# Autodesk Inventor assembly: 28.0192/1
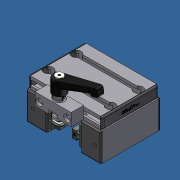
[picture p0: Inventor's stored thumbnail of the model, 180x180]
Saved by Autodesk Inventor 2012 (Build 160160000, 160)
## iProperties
Created: 2007-06
Part Number: 28.0192/1
Document SubType Name: Assembly
Designer: Andy Moles
Description: SLIDE LWN 32X45-45 WITH TOP CLAMP
Author: Andy Moles
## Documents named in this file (3)
- C:\Andys Backup Data\ANDY'S INVENTOR\INVENTOR LIBRARIES\PARTS LIBRARY\READY FOR USE MODULES LG\28.0192_1 SLIDE LWN 32X45-45 WITH TOP CLAMP.iam
- C:\Andys Backup Data\ANDY'S INVENTOR\INVENTOR LIBRARIES\PARTS LIBRARY\COMPONENTS LR\28.0270_9 SLIDE CLAMPING UNIT 5mm OFFSET..iam
- C:\Andys Backup Data\ANDY'S INVENTOR\INVENTOR LIBRARIES\PARTS LIBRARY\READY FOR USE MODULES LG\28.0192 SLIDE LWN 32X45-45.iam
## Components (2 placed, 2 different names)
1. 28.0270_9 SLIDE CLAMPING UNIT 5mm OFFSET.:1 [sub-assembly] — Mate:1, Mate:2, Flush:1
2. 28.0192 SLIDE LWN 32X45-45:1 [sub-assembly] — Mate:1, Mate:2, Flush:1
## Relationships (3: Mate 2, Flush 1)
- Mate:1: 28.0270_9 SLIDE CLAMPING UNIT 5mm OFFSET.:1 ↔ 28.0192 SLIDE LWN 32X45-45:1
- Mate:2: 28.0270_9 SLIDE CLAMPING UNIT 5mm OFFSET.:1 ↔ 28.0192 SLIDE LWN 32X45-45:1
- Flush:1: 28.0270_9 SLIDE CLAMPING UNIT 5mm OFFSET.:1 ↔ 28.0192 SLIDE LWN 32X45-45:1
